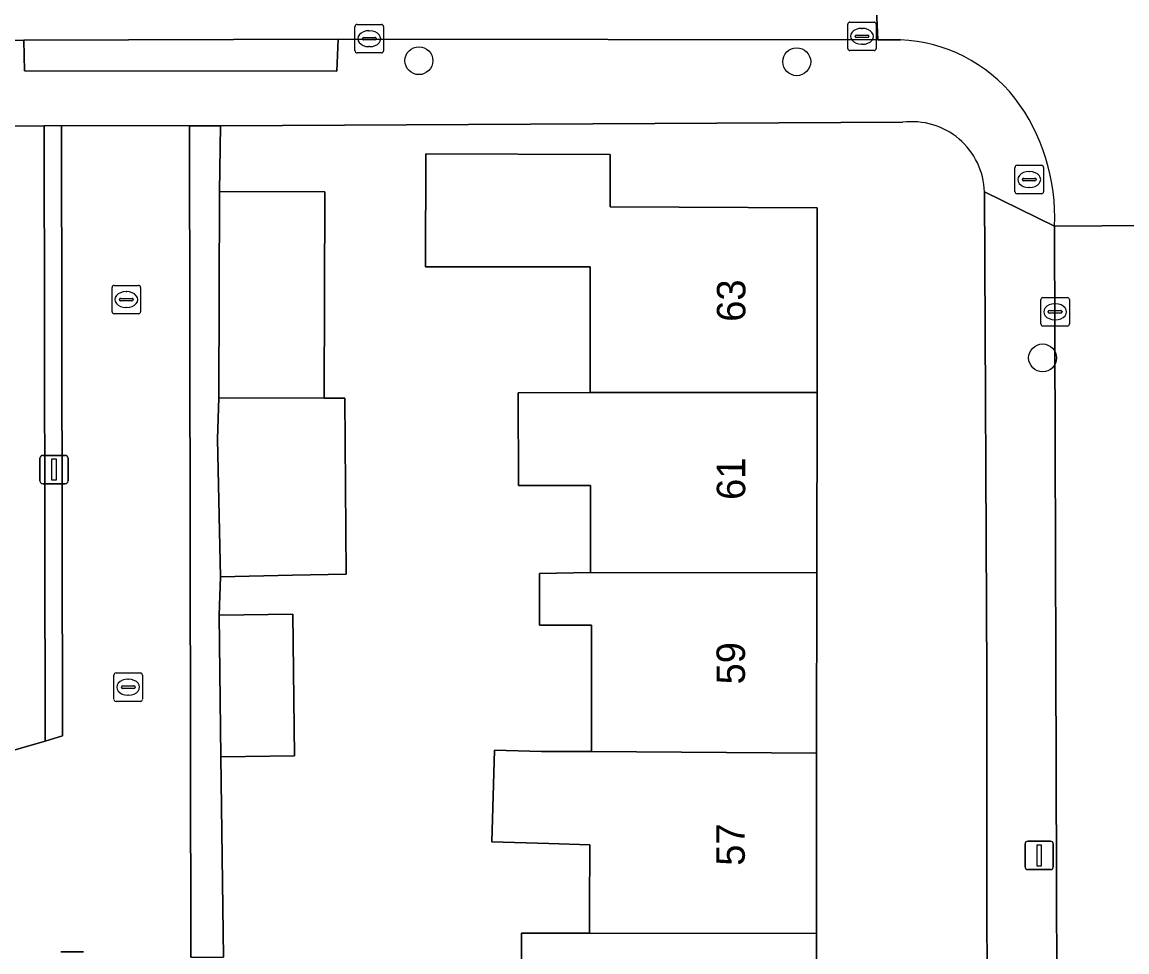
# Model space of a CAD drawing. Extents: x 160732 to 162107, y 387428 to 388479.
# Drawn here: x 161119.69 to 161158.48, y 388198.11 to 388230.78 of the extents above; entities that cross this region are included whole.
import ezdxf

# ---------------------------------------------------------------- set-up
doc = ezdxf.new("R2010")
doc.units = 0
for name, color, linetype in [('IMGEO_Boom', 7, 'Continuous'), ('IMGEO_Brandkraan', 7, 'Continuous'), ('IMGEO_Erf', 7, 'Continuous'), ('IMGEO_Kolk', 7, 'Continuous'), ('IMGEO_Lichtmast', 7, 'Continuous'), ('IMGEO_Muur', 7, 'Continuous'), ('IMGEO_Pand', 7, 'Continuous'), ('IMGEO_Pand_nummerreeks', 7, 'Continuous'), ('IMGEO_Rijbaan_lokaal_open', 7, 'Continuous'), ('IMGEO_Voetpad_open', 7, 'Continuous')]:
    doc.layers.add(name, color=color, linetype=linetype)

msp = doc.modelspace()

# ---------------------------------------------------------------- linework, layer by layer
at = {"layer": 'IMGEO_Boom'}
for centre in [(161133.623, 388229.425), (161146.891, 388229.388), (161155.522, 388218.983)]:
    msp.add_circle(centre, 0.489, dxfattribs=at)
at = {"layer": 'IMGEO_Brandkraan'}
for p, q in [((161154.554, 388224.823), (161154.554, 388225.675)), ((161154.629, 388225.749), (161155.481, 388225.749)), ((161155.042, 388225.529), (161155.067, 388225.529)), ((161155.555, 388225.675), (161155.555, 388224.823)), ((161154.813, 388225.243), (161154.813, 388225.255)), ((161155.251, 388225.206), (161154.853, 388225.206)), ((161154.856, 388225.292), (161155.254, 388225.292)), ((161155.297, 388225.255), (161155.297, 388225.243)), ((161155.481, 388224.749), (161154.629, 388224.749)), ((161155.065, 388224.969), (161155.04, 388224.969))]:
    msp.add_line(p, q, dxfattribs=at)
for points in [[(161154.554, 388224.823), (161154.554, 388225.675)], [(161154.629, 388225.749), (161155.481, 388225.749)], [(161155.555, 388225.675), (161155.555, 388224.823)], [(161155.481, 388224.749), (161154.629, 388224.749)]]:
    msp.add_lwpolyline(points, dxfattribs=at)
for centre, radius, start, end in [((161154.631, 388225.673), 0.0765, 91.552, 178.448), ((161154.631, 388225.673), 0.0765, 91.552, 178.448), ((161155.479, 388225.673), 0.0765, 1.552, 88.448), ((161155.479, 388225.673), 0.0765, 1.552, 88.448), ((161154.853, 388225.252), 0.0403, 85.8775, 175.7526), ((161154.85, 388225.242), 0.0366, 178.938, 274.7102), ((161155.254, 388225.249), 0.043, 264.8664, 352.4533), ((161155.258, 388225.254), 0.0386, 1.7309, 96.639), ((161154.631, 388224.825), 0.0765, 181.552, 268.448), ((161154.631, 388224.825), 0.0765, 181.552, 268.448), ((161155.479, 388224.825), 0.0765, 271.552, 358.448), ((161155.479, 388224.825), 0.0765, 271.552, 358.448)]:
    msp.add_arc(centre, radius, start, end, dxfattribs=at)
for centre, major_axis, ratio, start_param, end_param in [((161155.041, 388225.249), (-0.387, 0.002), 0.722429, 4.712389, 7.853982), ((161155.066, 388225.249), (-0.39, 0.002), 0.717154, 1.570796, 4.712389)]:
    msp.add_ellipse(centre, major_axis=major_axis, ratio=ratio, start_param=start_param, end_param=end_param, dxfattribs=at)
at = {"layer": 'IMGEO_Erf'}
for points in [[(161118.777, 388205.02), (161120.504, 388205.518), (161120.471, 388227.138), (161074.599, 388226.989)], [(161150.612, 388227.261), (161126.663, 388227.137), (161126.617, 388224.824), (161130.322, 388224.814), (161130.301, 388217.565), (161131.028, 388217.571), (161131.073, 388211.382), (161129.19, 388211.343), (161126.659, 388211.29), (161126.606, 388209.94), (161129.195, 388209.973), (161129.259, 388204.999), (161126.67, 388204.965), (161126.762, 388197.927)], [(161137.225, 388198.771), (161137.756, 388198.77), (161139.609, 388198.768), (161139.61, 388199.021), (161139.613, 388199.643), (161139.622, 388201.876), (161138.185, 388201.917), (161136.188, 388201.974), (161136.279, 388205.2), (161137.931, 388205.153), (161139.681, 388205.153), (161139.681, 388209.591), (161137.86, 388209.591), (161137.86, 388211.406), (161139.649, 388211.443), (161139.649, 388214.501), (161137.119, 388214.498), (161137.115, 388217.758), (161139.632, 388217.761), (161139.632, 388222.181), (161137.767, 388222.181), (161137.667, 388222.181), (161133.855, 388222.181), (161133.869, 388226.152), (161140.342, 388226.131), (161140.336, 388224.285), (161147.612, 388224.26), (161147.605, 388217.772), (161147.597, 388211.434), (161147.59, 388205.096), (161147.583, 388198.758), (161147.576, 388192.42)], [(161153.588, 388170.261), (161153.568, 388207.782), (161153.48, 388224.813)], [(161137.221, 388195.776), (161137.225, 388198.771)]]:
    msp.add_lwpolyline(points, dxfattribs=at)
msp.add_arc((161150.941, 388224.742), 2.54, 1.6053, 97.4295, dxfattribs=at)
at = {"layer": 'IMGEO_Kolk'}
for p, q in [((161131.38, 388229.773), (161131.38, 388230.625)), ((161131.455, 388230.699), (161132.307, 388230.699)), ((161132.381, 388230.625), (161132.381, 388229.773)), ((161148.682, 388229.856), (161148.682, 388230.708)), ((161148.757, 388230.782), (161149.609, 388230.782)), ((161149.17, 388230.562), (161149.195, 388230.562)), ((161149.683, 388230.708), (161149.683, 388229.856)), ((161131.639, 388230.193), (161131.639, 388230.205)), ((161132.077, 388230.156), (161131.679, 388230.156)), ((161131.682, 388230.242), (161132.08, 388230.242)), ((161131.868, 388230.479), (161131.893, 388230.479)), ((161132.123, 388230.205), (161132.123, 388230.193)), ((161148.941, 388230.276), (161148.941, 388230.288)), ((161149.379, 388230.239), (161148.981, 388230.239)), ((161148.984, 388230.325), (161149.382, 388230.325)), ((161149.425, 388230.288), (161149.425, 388230.276)), ((161131.891, 388229.919), (161131.866, 388229.919)), ((161149.609, 388229.782), (161148.757, 388229.782)), ((161149.193, 388230.002), (161149.168, 388230.002)), ((161132.307, 388229.699), (161131.455, 388229.699)), ((161122.851, 388220.605), (161122.851, 388221.457)), ((161122.926, 388221.531), (161123.778, 388221.531)), ((161123.339, 388221.311), (161123.364, 388221.311)), ((161123.852, 388221.457), (161123.852, 388220.605)), ((161123.11, 388221.025), (161123.11, 388221.037)), ((161123.548, 388220.988), (161123.15, 388220.988)), ((161123.153, 388221.074), (161123.551, 388221.074)), ((161123.594, 388221.037), (161123.594, 388221.025)), ((161155.462, 388220.177), (161155.462, 388221.029)), ((161155.537, 388221.103), (161156.389, 388221.103)), ((161155.95, 388220.883), (161155.975, 388220.883)), ((161156.463, 388221.029), (161156.463, 388220.177)), ((161123.778, 388220.531), (161122.926, 388220.531)), ((161123.362, 388220.751), (161123.337, 388220.751)), ((161155.721, 388220.597), (161155.721, 388220.609)), ((161156.159, 388220.56), (161155.761, 388220.56)), ((161155.764, 388220.646), (161156.162, 388220.646)), ((161156.205, 388220.609), (161156.205, 388220.597)), ((161156.389, 388220.103), (161155.537, 388220.103)), ((161155.973, 388220.323), (161155.948, 388220.323)), ((161122.917, 388206.985), (161122.917, 388207.837)), ((161122.992, 388207.911), (161123.844, 388207.911)), ((161123.405, 388207.691), (161123.43, 388207.691)), ((161123.918, 388207.837), (161123.918, 388206.985)), ((161123.176, 388207.405), (161123.176, 388207.417)), ((161123.614, 388207.368), (161123.216, 388207.368)), ((161123.219, 388207.454), (161123.617, 388207.454)), ((161123.66, 388207.417), (161123.66, 388207.405)), ((161123.844, 388206.911), (161122.992, 388206.911)), ((161123.428, 388207.131), (161123.403, 388207.131))]:
    msp.add_line(p, q, dxfattribs=at)
for points in [[(161131.38, 388229.773), (161131.38, 388230.625)], [(161131.455, 388230.699), (161132.307, 388230.699)], [(161132.381, 388230.625), (161132.381, 388229.773)], [(161148.682, 388229.856), (161148.682, 388230.708)], [(161148.757, 388230.782), (161149.609, 388230.782)], [(161149.683, 388230.708), (161149.683, 388229.856)], [(161149.609, 388229.782), (161148.757, 388229.782)], [(161132.307, 388229.699), (161131.455, 388229.699)], [(161122.851, 388220.605), (161122.851, 388221.457)], [(161122.926, 388221.531), (161123.778, 388221.531)], [(161123.852, 388221.457), (161123.852, 388220.605)], [(161155.462, 388220.177), (161155.462, 388221.029)], [(161155.537, 388221.103), (161156.389, 388221.103)], [(161156.463, 388221.029), (161156.463, 388220.177)], [(161123.778, 388220.531), (161122.926, 388220.531)], [(161156.389, 388220.103), (161155.537, 388220.103)], [(161122.917, 388206.985), (161122.917, 388207.837)], [(161122.992, 388207.911), (161123.844, 388207.911)], [(161123.918, 388207.837), (161123.918, 388206.985)], [(161123.844, 388206.911), (161122.992, 388206.911)]]:
    msp.add_lwpolyline(points, dxfattribs=at)
for centre, radius, start, end in [((161131.457, 388230.623), 0.0765, 91.552, 178.448), ((161131.457, 388230.623), 0.0765, 91.552, 178.448), ((161132.305, 388230.623), 0.0765, 1.552, 88.448), ((161132.305, 388230.623), 0.0765, 1.552, 88.448), ((161148.759, 388230.706), 0.0765, 91.552, 178.448), ((161148.759, 388230.706), 0.0765, 91.552, 178.448), ((161149.607, 388230.706), 0.0765, 1.552, 88.448), ((161149.607, 388230.706), 0.0765, 1.552, 88.448), ((161131.679, 388230.202), 0.0403, 85.8775, 175.7526), ((161131.676, 388230.192), 0.0366, 178.938, 274.7102), ((161132.08, 388230.199), 0.043, 264.8664, 352.4533), ((161132.084, 388230.204), 0.0386, 1.7309, 96.639), ((161148.981, 388230.285), 0.0403, 85.8775, 175.7526), ((161148.978, 388230.275), 0.0366, 178.938, 274.7102), ((161149.382, 388230.282), 0.043, 264.8664, 352.4533), ((161149.386, 388230.287), 0.0386, 1.7309, 96.639), ((161131.457, 388229.775), 0.0765, 181.552, 268.448), ((161131.457, 388229.775), 0.0765, 181.552, 268.448), ((161132.305, 388229.775), 0.0765, 271.552, 358.448), ((161132.305, 388229.775), 0.0765, 271.552, 358.448), ((161148.759, 388229.858), 0.0765, 181.552, 268.448), ((161148.759, 388229.858), 0.0765, 181.552, 268.448), ((161149.607, 388229.858), 0.0765, 271.552, 358.448), ((161149.607, 388229.858), 0.0765, 271.552, 358.448), ((161122.928, 388221.455), 0.0765, 91.552, 178.448), ((161122.928, 388221.455), 0.0765, 91.552, 178.448), ((161123.776, 388221.455), 0.0765, 1.552, 88.448), ((161123.776, 388221.455), 0.0765, 1.552, 88.448), ((161123.15, 388221.034), 0.0403, 85.8775, 175.7526), ((161123.147, 388221.024), 0.0366, 178.938, 274.7102), ((161123.551, 388221.031), 0.043, 264.8664, 352.4533), ((161123.555, 388221.036), 0.0386, 1.7309, 96.639), ((161155.539, 388221.027), 0.0765, 91.552, 178.448), ((161155.539, 388221.027), 0.0765, 91.552, 178.448), ((161156.387, 388221.027), 0.0765, 1.552, 88.448), ((161156.387, 388221.027), 0.0765, 1.552, 88.448), ((161122.928, 388220.607), 0.0765, 181.552, 268.448), ((161122.928, 388220.607), 0.0765, 181.552, 268.448), ((161123.776, 388220.607), 0.0765, 271.552, 358.448), ((161123.776, 388220.607), 0.0765, 271.552, 358.448), ((161155.761, 388220.606), 0.0403, 85.8775, 175.7526), ((161155.758, 388220.596), 0.0366, 178.938, 274.7102), ((161156.162, 388220.603), 0.043, 264.8664, 352.4533), ((161156.166, 388220.608), 0.0386, 1.7309, 96.639), ((161155.539, 388220.179), 0.0765, 181.552, 268.448), ((161155.539, 388220.179), 0.0765, 181.552, 268.448), ((161156.387, 388220.179), 0.0765, 271.552, 358.448), ((161156.387, 388220.179), 0.0765, 271.552, 358.448), ((161122.994, 388207.835), 0.0765, 91.552, 178.448), ((161122.994, 388207.835), 0.0765, 91.552, 178.448), ((161123.842, 388207.835), 0.0765, 1.552, 88.448), ((161123.842, 388207.835), 0.0765, 1.552, 88.448), ((161123.216, 388207.414), 0.0403, 85.8775, 175.7526), ((161123.213, 388207.404), 0.0366, 178.938, 274.7102), ((161123.617, 388207.411), 0.043, 264.8664, 352.4533), ((161123.621, 388207.416), 0.0386, 1.7309, 96.639), ((161122.994, 388206.987), 0.0765, 181.552, 268.448), ((161122.994, 388206.987), 0.0765, 181.552, 268.448), ((161123.842, 388206.987), 0.0765, 271.552, 358.448), ((161123.842, 388206.987), 0.0765, 271.552, 358.448)]:
    msp.add_arc(centre, radius, start, end, dxfattribs=at)
for centre, major_axis, ratio, start_param, end_param in [((161149.169, 388230.282), (-0.387, 0.002), 0.722429, 4.712389, 7.853982), ((161149.194, 388230.282), (-0.39, 0.002), 0.717154, 1.570796, 4.712389), ((161131.867, 388230.199), (-0.387, 0.002), 0.722429, 4.712389, 7.853982), ((161131.892, 388230.199), (-0.39, 0.002), 0.717154, 1.570796, 4.712389), ((161123.338, 388221.031), (-0.387, 0.002), 0.722429, 4.712389, 7.853982), ((161123.363, 388221.031), (-0.39, 0.002), 0.717154, 1.570796, 4.712389), ((161155.949, 388220.603), (-0.387, 0.002), 0.722429, 4.712389, 7.853982), ((161155.974, 388220.603), (-0.39, 0.002), 0.717154, 1.570796, 4.712389), ((161123.404, 388207.411), (-0.387, 0.002), 0.722429, 4.712389, 7.853982), ((161123.429, 388207.411), (-0.39, 0.002), 0.717154, 1.570796, 4.712389)]:
    msp.add_ellipse(centre, major_axis=major_axis, ratio=ratio, start_param=start_param, end_param=end_param, dxfattribs=at)
at = {"layer": 'IMGEO_Lichtmast'}
for p, q in [((161120.314, 388214.658), (161120.314, 388215.458)), ((161120.314, 388215.458), (161120.314, 388214.658)), ((161120.414, 388215.558), (161121.204, 388215.558)), ((161121.204, 388215.558), (161120.414, 388215.558)), ((161121.304, 388215.458), (161121.304, 388214.658)), ((161121.304, 388214.658), (161121.304, 388215.458)), ((161121.204, 388214.558), (161120.414, 388214.558)), ((161120.414, 388214.558), (161121.204, 388214.558)), ((161154.908, 388201.102), (161154.908, 388201.902)), ((161154.908, 388201.902), (161154.908, 388201.102)), ((161155.008, 388202.002), (161155.798, 388202.002)), ((161155.798, 388202.002), (161155.008, 388202.002)), ((161155.898, 388201.902), (161155.898, 388201.102)), ((161155.898, 388201.102), (161155.898, 388201.902)), ((161155.798, 388201.002), (161155.008, 388201.002)), ((161155.008, 388201.002), (161155.798, 388201.002)), ((161121.056, 388198.11), (161121.846, 388198.11)), ((161121.846, 388198.11), (161121.056, 388198.11))]:
    msp.add_line(p, q, dxfattribs=at)
for points in [[(161120.734, 388215.433), (161120.884, 388215.433), (161120.884, 388214.683), (161120.734, 388214.683), (161120.734, 388215.433)], [(161155.328, 388201.877), (161155.478, 388201.877), (161155.478, 388201.127), (161155.328, 388201.127), (161155.328, 388201.877)]]:
    msp.add_lwpolyline(points, dxfattribs=at)
for centre, start, end in [((161120.414, 388215.458), 90, 180), ((161120.414, 388215.458), 90, 180), ((161121.204, 388215.458), 0, 90), ((161121.204, 388215.458), 360, 90), ((161120.414, 388214.658), 180, 270), ((161120.414, 388214.658), 180, 270), ((161121.204, 388214.658), 270, 0), ((161121.204, 388214.658), 270, 0), ((161155.008, 388201.902), 90, 180), ((161155.008, 388201.902), 90, 180), ((161155.798, 388201.902), 0, 90), ((161155.798, 388201.902), 360, 90), ((161155.008, 388201.102), 180, 270), ((161155.008, 388201.102), 180, 270), ((161155.798, 388201.102), 270, 0), ((161155.798, 388201.102), 270, 0)]:
    msp.add_arc(centre, 0.1, start, end, dxfattribs=at)
at = {"layer": 'IMGEO_Muur'}
msp.add_lwpolyline([(161126.67, 388204.965), (161126.762, 388197.927)], dxfattribs=at)
at = {"layer": 'IMGEO_Pand'}
for points in [[(161147.605, 388217.772), (161147.612, 388224.26), (161140.336, 388224.285), (161140.342, 388226.131), (161133.869, 388226.152), (161133.855, 388222.181), (161137.667, 388222.181), (161137.767, 388222.181), (161139.632, 388222.181), (161139.632, 388217.761)], [(161126.596, 388217.575), (161130.301, 388217.565), (161130.322, 388224.814), (161126.617, 388224.824)], [(161147.605, 388217.772), (161139.632, 388217.761), (161137.115, 388217.758), (161137.119, 388214.498), (161139.649, 388214.501), (161139.649, 388211.443), (161147.597, 388211.434)], [(161130.301, 388217.565), (161126.596, 388217.575), (161126.557, 388216.125), (161126.659, 388211.29), (161129.19, 388211.343), (161131.073, 388211.382), (161131.028, 388217.571)], [(161139.649, 388211.443), (161137.86, 388211.406), (161137.86, 388209.591), (161139.681, 388209.591), (161139.681, 388205.153), (161147.59, 388205.096), (161147.597, 388211.434)], [(161126.67, 388204.965), (161129.259, 388204.999), (161129.195, 388209.973), (161126.606, 388209.94)], [(161147.59, 388205.096), (161139.681, 388205.153), (161137.931, 388205.153), (161136.279, 388205.2), (161136.188, 388201.974), (161138.185, 388201.917), (161139.622, 388201.876), (161139.613, 388199.643), (161139.61, 388199.021), (161139.609, 388198.768), (161147.583, 388198.758)], [(161147.583, 388198.758), (161139.609, 388198.768), (161137.756, 388198.77), (161137.225, 388198.771), (161137.221, 388195.776), (161139.529, 388195.773), (161139.531, 388192.418), (161147.576, 388192.42)]]:
    msp.add_lwpolyline(points, close=True, dxfattribs=at)
at = {"layer": 'IMGEO_Rijbaan_lokaal_open'}
for points in [[(161031.507, 388229.986), (161033.478, 388229.932), (161048.822, 388229.96), (161052.37, 388230.031), (161065.504, 388230.06), (161075.503, 388230.076), (161119.757, 388230.149), (161130.785, 388230.186), (161149.736, 388230.154), (161149.51, 388235.15)], [(161149.51, 388235.15), (161149.736, 388230.154), (161150.532, 388230.153)], [(161155.942, 388223.612), (161160.943, 388223.645), (161160.916, 388232.24), (161160.932, 388232.831)], [(161125.617, 388197.928), (161125.564, 388227.132), (161121.078, 388227.145), (161121.114, 388205.701), (161120.504, 388205.518), (161118.777, 388205.02), (161105.3, 388201.027), (161106.311, 388197.705)], [(161160.946, 388193.594), (161160.967, 388195.059), (161160.943, 388223.645), (161155.942, 388223.612), (161156.12, 388166.254), (161156.114, 388161.291), (161156.023, 388141.534), (161161.118, 388141.556), (161160.945, 388175.907)]]:
    msp.add_lwpolyline(points, dxfattribs=at)
for centre, radius, start, end in [((161150.328, 388224.766), 5.391, 38.3929, 87.829), ((161149.017, 388223.941), 6.932, 357.281, 37.0121)]:
    msp.add_arc(centre, radius, start, end, dxfattribs=at)
at = {"layer": 'IMGEO_Voetpad_open'}
for points in [[(161150.532, 388230.153), (161149.736, 388230.154), (161130.785, 388230.186), (161130.748, 388229.063), (161119.777, 388229.065), (161119.757, 388230.149), (161075.503, 388230.076), (161075.477, 388228.97), (161064.507, 388228.939), (161064.472, 388225.06), (161053.394, 388225.023), (161053.426, 388229.075)], [(161074.599, 388226.989), (161120.471, 388227.138), (161121.078, 388227.145), (161125.564, 388227.132), (161126.663, 388227.137), (161150.612, 388227.261)], [(161153.48, 388224.813), (161155.942, 388223.612)], [(161156.114, 388161.291), (161155.002, 388161.286), (161154.974, 388166.212), (161156.12, 388166.254), (161155.942, 388223.612), (161153.48, 388224.813), (161153.568, 388207.782), (161153.588, 388170.261), (161153.606, 388166.499), (161153.611, 388165.456), (161153.729, 388141.259), (161154.265, 388136.704)]]:
    msp.add_lwpolyline(points, dxfattribs=at)
for points in [[(161130.785, 388230.186), (161119.757, 388230.149), (161119.777, 388229.065), (161130.748, 388229.063)], [(161120.504, 388205.518), (161121.114, 388205.701), (161121.078, 388227.145), (161120.471, 388227.138)], [(161126.67, 388204.965), (161126.606, 388209.94), (161126.659, 388211.29), (161126.557, 388216.125), (161126.596, 388217.575), (161126.617, 388224.824), (161126.663, 388227.137), (161125.564, 388227.132), (161125.617, 388197.928), (161125.806, 388197.928), (161126.762, 388197.927)]]:
    msp.add_lwpolyline(points, close=True, dxfattribs=at)
for centre, radius, start, end in [((161150.328, 388224.766), 5.391, 38.3929, 87.829), ((161149.017, 388223.941), 6.932, 357.281, 37.0121), ((161150.941, 388224.742), 2.54, 1.6053, 97.4295)]:
    msp.add_arc(centre, radius, start, end, dxfattribs=at)

# ---------------------------------------------------------------- texts
at = {"layer": 'IMGEO_Pand_nummerreeks'}
for s, rotation, p in [('63', 89.9351, (161145.087, 388220.251)), ('61', 89.9372, (161145.081, 388213.992)), ('59', 89.9351, (161145.073, 388207.508)), ('57', 89.9372, (161145.066, 388201.136))]:
    msp.add_text(s, height=1, rotation=rotation, dxfattribs=at).set_placement(p)

doc.saveas('drawing.dxf')
